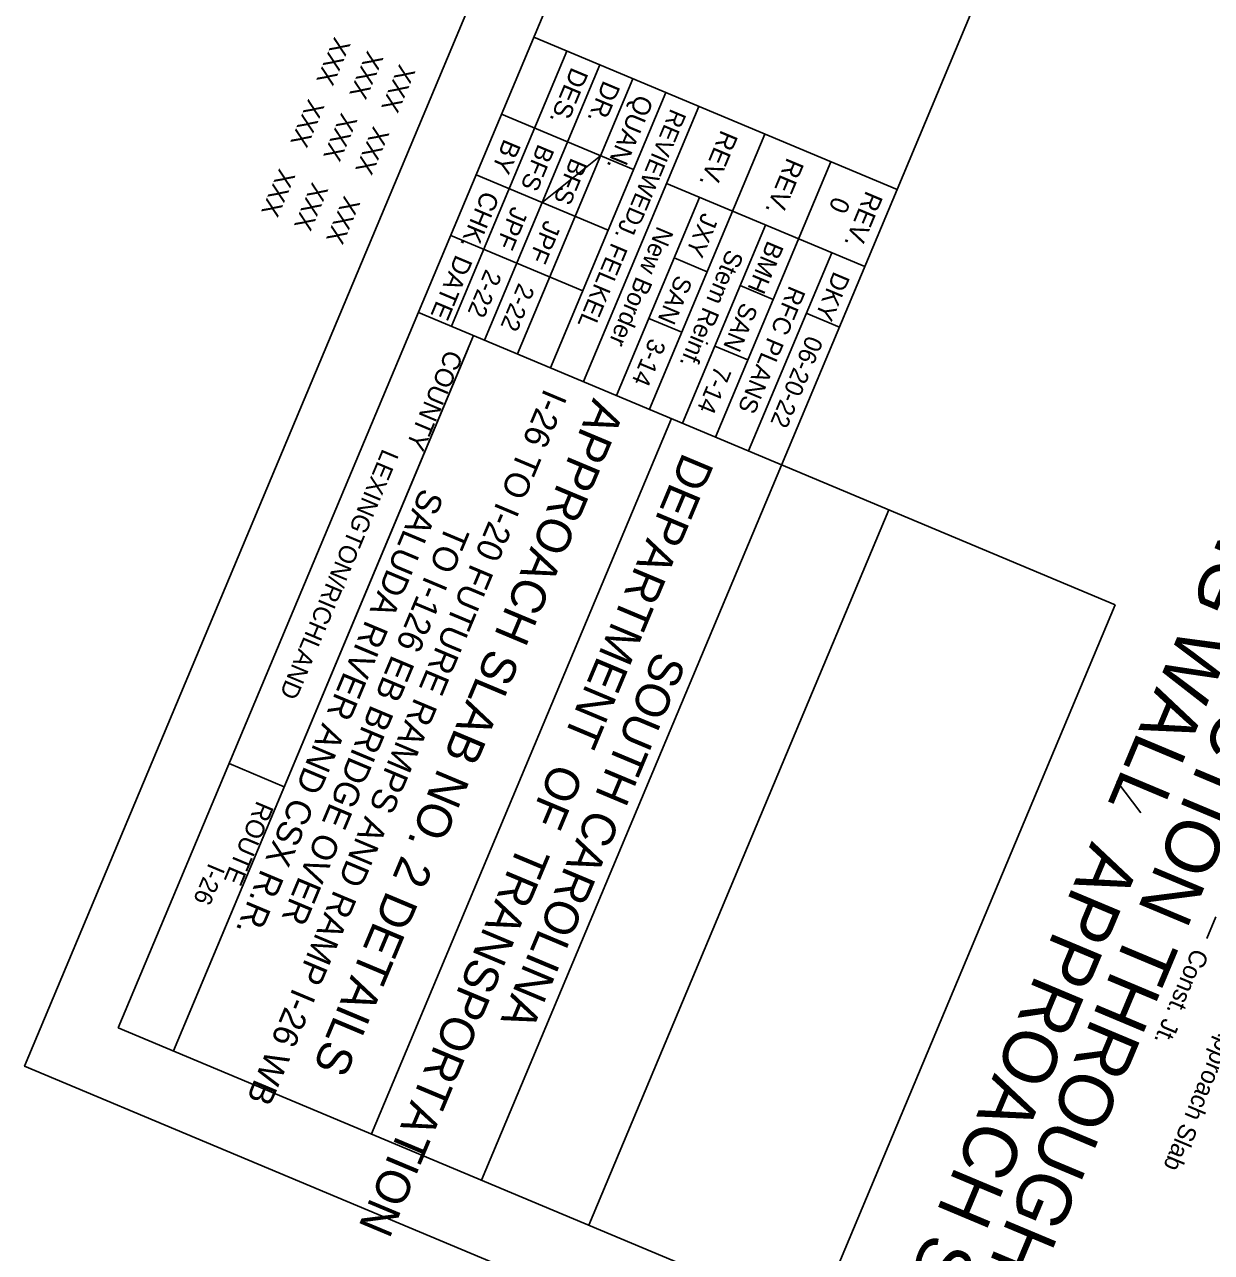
# Model space of a CAD drawing. Extents: x 1968564 to 1968711, y 796599 to 796794.
# Drawn here: x 1968563.85 to 1968596.99, y 796627.75 to 796662.05 of the extents above; entities that cross this region are included whole.
import ezdxf

# ---------------------------------------------------------------- set-up
doc = ezdxf.new("R2010")
doc.units = 0
for name, color, linetype in [('BR_AUTO DIMENSION', 7, 'Continuous'), ('BR_BORDER LINES', 7, 'Continuous'), ('BR_TEXT', 7, 'Continuous'), ('Level 31', 7, 'Continuous')]:
    doc.layers.add(name, color=color, linetype=linetype)

msp = doc.modelspace()

# ---------------------------------------------------------------- linework, layer by layer
at = {"layer": 'BR_AUTO DIMENSION'}
msp.add_line((1968596.86, 796636.522), (1968597.114, 796637.128), dxfattribs=at)
at = {"layer": 'BR_BORDER LINES'}
for p, q in [((1968618.549, 796758.212), (1968566.464, 796634.028)), ((1968596.513, 796677.23), (1968588.212, 796657.44)), ((1968578.068, 796661.695), (1968588.212, 796657.44)), ((1968578.99, 796661.308), (1968575.767, 796653.623)), ((1968579.912, 796660.921), (1968576.689, 796653.236)), ((1968580.835, 796660.534), (1968577.611, 796652.849)), ((1968581.757, 796660.147), (1968578.534, 796652.462)), ((1968582.679, 796659.761), (1968579.456, 796652.076)), ((1968580.854, 796657.996), (1968577.166, 796659.543)), ((1968584.524, 796658.987), (1968581.3, 796651.302)), ((1968586.368, 796658.213), (1968583.145, 796650.528)), ((1968580.145, 796656.305), (1968576.456, 796657.852)), ((1968587.31, 796655.288), (1968581.777, 796657.609)), ((1968588.212, 796657.44), (1968576.609, 796629.774)), ((1968582.699, 796657.222), (1968580.378, 796651.689)), ((1968584.543, 796656.448), (1968582.222, 796650.915)), ((1968579.436, 796654.614), (1968575.747, 796656.161)), ((1968581.99, 796655.531), (1968582.912, 796655.145)), ((1968586.388, 796655.675), (1968584.067, 796650.142)), ((1968583.834, 796654.758), (1968584.756, 796654.371)), ((1968574.845, 796654.01), (1968594.308, 796645.846)), ((1968581.281, 796653.841), (1968582.203, 796653.454)), ((1968585.679, 796653.984), (1968586.601, 796653.597)), ((1968576.382, 796653.365), (1968568.001, 796633.384)), ((1968576.231, 796653.005), (1968568.001, 796633.384)), ((1968583.125, 796653.067), (1968584.047, 796652.68)), ((1968581.915, 796651.044), (1968573.534, 796631.062)), ((1968581.915, 796651.044), (1968581.915, 796651.044)), ((1968587.983, 796648.498), (1968579.603, 796628.518)), ((1968594.308, 796645.846), (1968585.928, 796625.865)), ((1968569.559, 796641.406), (1968571.096, 796640.761)), ((1968566.464, 796634.028), (1968643.927, 796601.539))]:
    msp.add_line(p, q, dxfattribs=at)
at = {"layer": 'BR_TEXT'}
msp.add_line((1968595.026, 796640.031), (1968594.348, 796640.921), dxfattribs=at)
at = {"layer": 'Level 31'}
for p, q in [((1968579.932, 796658.382), (1968578.301, 796657.078)), ((1968576.101, 796641.734), (1968576.101, 796641.734))]:
    msp.add_line(p, q, dxfattribs=at)
msp.add_lwpolyline([(1968619.541, 796765.748), (1968563.846, 796632.955), (1968644.997, 796598.919), (1968700.693, 796731.712)], close=True, dxfattribs=at)

# ---------------------------------------------------------------- texts
at = {"layer": 'BR_TEXT'}
for s, height, p in [('XXX', 0.5, (1968572.504, 796661.724)), ('XXX', 0.5, (1968573.423, 796661.339)), ('XXX', 0.5, (1968574.316, 796660.964)), ('DES.', 0.52, (1968579.126, 796660.884)), ('DR.', 0.52, (1968580.018, 796660.514)), ('QUAN.', 0.52, (1968580.946, 796660.126)), ('XXX', 0.5, (1968571.777, 796659.991)), ('REVIEWED', 0.48, (1968581.898, 796659.724)), ('XXX', 0.5, (1968572.696, 796659.605)), ('XXX', 0.5, (1968573.589, 796659.231)), ('REV.', 0.52, (1968583.306, 796659.13)), ('BY', 0.52, (1968577.243, 796658.88)), ('BFS', 0.5, (1968578.195, 796658.737)), ('BFS', 0.5, (1968579.114, 796658.352)), ('REV.', 0.52, (1968585.15, 796658.357)), ('XXX', 0.5, (1968570.963, 796658.05)), ('XXX', 0.5, (1968571.882, 796657.665)), ('XXX', 0.5, (1968572.776, 796657.29)), ('CHK.', 0.52, (1968576.643, 796657.436)), ('REV.', 0.52, (1968587.354, 796657.432)), ('JPF', 0.5, (1968577.464, 796656.995)), ('0', 0.52, (1968586.443, 796657.277)), ('JPF', 0.5, (1968578.383, 796656.61)), ('J. FELKEL', 0.5, (1968580.518, 796656.631)), ('JXY', 0.5, (1968582.78, 796656.818)), ('New Border', 0.5, (1968581.524, 796656.443)), ('BMH', 0.5, (1968584.602, 796656.04)), ('DATE', 0.52, (1968575.893, 796655.646)), ('Stem Reinf.', 0.5, (1968583.48, 796655.8)), ('2-22', 0.5, (1968576.728, 796655.239)), ('SAN', 0.5, (1968582.052, 796655.081)), ('DKY', 0.5, (1968586.45, 796655.179)), ('2-22', 0.5, (1968577.647, 796654.854)), ('RFC PLANS', 0.5, (1968585.21, 796654.781)), ('SAN', 0.5, (1968583.879, 796654.315)), ('3-14', 0.5, (1968581.312, 796653.317)), ('06-20-22', 0.5, (1968585.701, 796653.392)), ('COUNTY', 0.52, (1968575.628, 796652.999)), ('7-14', 0.5, (1968583.139, 796652.55)), ('I-26 TO I-20 FUTURE RAMPS AND RAMP I-26 WB', 0.7, (1968578.367, 796651.91)), ('APPROACH SLAB NO. 2 DETAILS', 0.96, (1968579.735, 796651.639)), ('WING WALL  APPROACH SLAB', 1.5, (1968598.522, 796650.871)), ('LEXINGTON/RICHLAND', 0.49998, (1968573.848, 796650.223)), ('DEPARTMENT  OF  TRANSPORTATION', 0.94348, (1968582.243, 796650.129)), ('SALUDA RIVER AND CSX R.R.', 0.7, (1968574.926, 796649.136)), ('TO I-126 EB BRIDGE OVER', 0.7, (1968575.638, 796648.118)), ('SECTION THROUGH', 1.5, (1968598.361, 796645.546)), ('SOUTH CAROLINA', 0.94348, (1968581.47, 796644.586)), ('ROUTE', 0.52, (1968570.342, 796640.395)), ('I-26', 0.5, (1968568.996, 796638.655)), ('Const. Jt.', 0.5, (1968596.473, 796636.276)), ('Approach Slab', 0.5, (1968597.338, 796634.203))]:
    msp.add_text(s, height=height, rotation=247.246, dxfattribs=at).set_placement(p)

doc.saveas('drawing.dxf')
